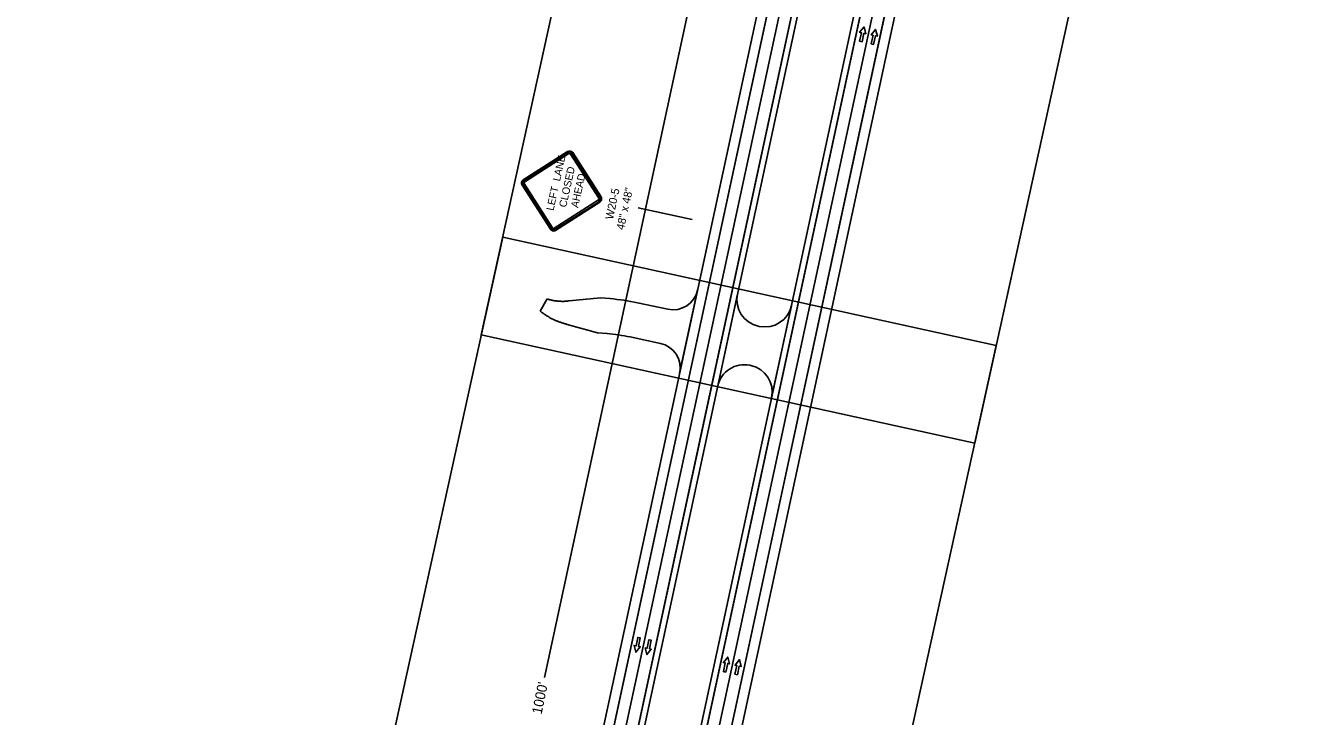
# Model space of a CAD drawing. Extents: x 14104283 to 14120882, y 8635219 to 8671666.
# Drawn here: x 14108141 to 14109426, y 8643764 to 8644454 of the extents above; entities that cross this region are included whole.
import ezdxf

# ---------------------------------------------------------------- set-up
doc = ezdxf.new("R2010")
doc.units = 0
for name, color, linetype in [('Cell', 7, 'Continuous'), ('dsnNonPlotable', 7, 'Continuous'), ('dsnPaintExistingEdgeLineRightWhite', 7, 'Continuous'), ('dsnPaintPlaceBrokenLineWhite', 7, 'Continuous'), ('dsnPaintPlaceEdgeLineLeftYellow', 7, 'Continuous'), ('dsnPaintPlaceEdgeLineRightWhite', 7, 'Continuous'), ('dsnPaintRemoveDoubleCenterLineYellow', 7, 'Continuous'), ('dsnShadingPaved', 7, 'Continuous'), ('dsnStdLabel', 7, 'Continuous'), ('dsnStgShadingPrevPav', 7, 'Continuous')]:
    doc.layers.add(name, color=color, linetype=linetype)

msp = doc.modelspace()

# ---------------------------------------------------------------- linework, layer by layer
at = {"layer": 'Cell'}
for p, q in [((14108682.3, 8644328.2), (14108638.1, 8644299.9)), ((14108682.8, 8644327.4), (14108683.7, 8644326.1)), ((14108685.4, 8644325.7), (14108686.7, 8644326.6)), ((14108715.8, 8644282.8), (14108687.5, 8644327.1)), ((14108637, 8644294.7), (14108665.3, 8644250.5)), ((14108637.8, 8644295.2), (14108639.1, 8644296.1)), ((14108639.5, 8644297.8), (14108638.6, 8644299.1)), ((14108670.4, 8644249.4), (14108714.7, 8644277.7)), ((14108713.3, 8644279.8), (14108714.2, 8644278.4)), ((14108715, 8644282.3), (14108713.7, 8644281.5)), ((14108667.4, 8644251.8), (14108666.1, 8644251)), ((14108669.9, 8644250.2), (14108669.1, 8644251.5))]:
    msp.add_line(p, q, dxfattribs=at)
for points in [[(14108976.7, 8644437.9), (14108974.3, 8644438.4), (14108976.1, 8644447), (14108974.3, 8644447.4), (14108978.7, 8644452.8), (14108980.4, 8644446), (14108978.6, 8644446.4)], [(14108988.3, 8644435.3), (14108985.9, 8644435.9), (14108987.7, 8644444.4), (14108985.9, 8644444.8), (14108990.3, 8644450.3), (14108992, 8644443.5), (14108990.2, 8644443.9)], [(14108682.8, 8644327.4), (14108638.6, 8644299.1), (14108639.5, 8644297.8), (14108683.7, 8644326.1), (14108682.8, 8644327.4)], [(14108715, 8644282.3), (14108686.7, 8644326.6), (14108685.4, 8644325.7), (14108713.7, 8644281.5), (14108715, 8644282.3)], [(14108637.8, 8644295.2), (14108666.1, 8644251), (14108667.4, 8644251.8), (14108639.1, 8644296.1), (14108637.8, 8644295.2)], [(14108669.9, 8644250.2), (14108714.2, 8644278.4), (14108713.3, 8644279.8), (14108669.1, 8644251.5), (14108669.9, 8644250.2)], [(14108752.6, 8643842.5), (14108755.1, 8643842), (14108753.2, 8643833.5), (14108755.1, 8643833.1), (14108750.7, 8643827.6), (14108748.9, 8643834.4), (14108750.8, 8643834)], [(14108763.7, 8643840.1), (14108766.1, 8643839.6), (14108764.3, 8643831), (14108766.1, 8643830.6), (14108761.7, 8643825.2), (14108760, 8643832), (14108761.8, 8643831.6)], [(14108840.5, 8643807.8), (14108838.1, 8643808.3), (14108839.9, 8643816.9), (14108838.1, 8643817.3), (14108842.5, 8643822.7), (14108844.2, 8643816), (14108842.4, 8643816.4)], [(14108852.2, 8643805.2), (14108849.7, 8643805.8), (14108851.6, 8643814.3), (14108849.8, 8643814.7), (14108854.1, 8643820.2), (14108855.9, 8643813.4), (14108854, 8643813.8)]]:
    msp.add_lwpolyline(points, close=True, dxfattribs=at)
for points in [[(14108978.6, 8644446.4), (14108980.4, 8644446), (14108978.7, 8644452.8), (14108974.3, 8644447.4), (14108976.1, 8644447), (14108974.3, 8644438.4), (14108976.7, 8644437.9), (14108978.6, 8644446.4)], [(14108990.2, 8644443.9), (14108992, 8644443.5), (14108990.3, 8644450.3), (14108985.9, 8644444.8), (14108987.7, 8644444.4), (14108985.9, 8644435.9), (14108988.3, 8644435.3), (14108990.2, 8644443.9)], [(14108750.8, 8643834), (14108748.9, 8643834.4), (14108750.7, 8643827.6), (14108755.1, 8643833.1), (14108753.2, 8643833.5), (14108755.1, 8643842), (14108752.6, 8643842.5), (14108750.8, 8643834)], [(14108761.8, 8643831.6), (14108760, 8643832), (14108761.7, 8643825.2), (14108766.1, 8643830.6), (14108764.3, 8643831), (14108766.1, 8643839.6), (14108763.7, 8643840.1), (14108761.8, 8643831.6)], [(14108842.4, 8643816.4), (14108844.2, 8643816), (14108842.5, 8643822.7), (14108838.1, 8643817.3), (14108839.9, 8643816.9), (14108838.1, 8643808.3), (14108840.5, 8643807.8), (14108842.4, 8643816.4)], [(14108854, 8643813.8), (14108855.9, 8643813.4), (14108854.1, 8643820.2), (14108849.8, 8643814.7), (14108851.6, 8643814.3), (14108849.7, 8643805.8), (14108852.2, 8643805.2), (14108854, 8643813.8)]]:
    msp.add_lwpolyline(points, dxfattribs=at)
for centre, radius, start, end in [((14108684.4, 8644325), 3.75, 32.608, 122.6076), ((14108684.4, 8644325), 2.81, 32.608, 122.6076), ((14108684.4, 8644325), 1.25, 32.608, 122.6076), ((14108640.1, 8644296.7), 3.75, 122.6078, 212.6076), ((14108640.1, 8644296.7), 2.81, 122.6078, 212.6076), ((14108640.1, 8644296.7), 1.25, 122.6078, 212.6076), ((14108712.7, 8644280.8), 1.25, 302.6078, 32.608), ((14108712.7, 8644280.8), 2.81, 302.6078, 32.608), ((14108712.7, 8644280.8), 3.75, 302.6078, 32.608), ((14108668.4, 8644252.5), 3.75, 212.6076, 302.6078), ((14108668.4, 8644252.5), 2.81, 212.6076, 302.6078), ((14108668.4, 8644252.5), 1.25, 212.6076, 302.6078)]:
    msp.add_arc(centre, radius, start, end, dxfattribs=at)
at = {"layer": 'dsnNonPlotable'}
for points in [[(14108596.1, 8644144.9), (14108932.5, 8645675.8), (14109425.7, 8645567.5), (14109089.3, 8644036.5)], [(14108281.2, 8642711.6), (14108617.6, 8644242.5), (14109110.8, 8644134.2), (14108774.4, 8642603.2)]]:
    msp.add_lwpolyline(points, close=True, dxfattribs=at)
at = {"layer": 'dsnPaintExistingEdgeLineRightWhite'}
msp.add_line((14108724, 8643185.8), (14109088.7, 8644879.7), dxfattribs=at)
at = {"layer": 'dsnPaintPlaceBrokenLineWhite'}
msp.add_line((14108623.3, 8643207.7), (14108988, 8644901.3), dxfattribs=at)
msp.add_lwpolyline([(14108306.4, 8641340.7), (14108389, 8641717), (14108712.3, 8643188.3), (14108894.6, 8644035.3), (14109077, 8644882.2)], dxfattribs=at)
at = {"layer": 'dsnPaintPlaceEdgeLineLeftYellow'}
msp.add_line((14108700.5, 8643190.8), (14109065.3, 8644884.7), dxfattribs=at)
msp.add_lwpolyline([(14108999.8, 8644898.8), (14108635.1, 8643205.1), (14108434.9, 8642294.1)], dxfattribs=at)
at = {"layer": 'dsnPaintPlaceEdgeLineRightWhite'}
msp.add_lwpolyline([(14108976.3, 8644903.9), (14108611.6, 8643210.2), (14108202.1, 8641346.1)], dxfattribs=at)
at = {"layer": 'dsnPaintRemoveDoubleCenterLineYellow'}
msp.add_lwpolyline([(14108306.4, 8641340.7), (14108389, 8641717), (14108712.3, 8643188.3), (14108894.6, 8644035.3), (14109077, 8644882.2)], dxfattribs=at)
at = {"layer": 'dsnShadingPaved'}
for points in [[(14108976.3, 8644903.9), (14108611.6, 8643210.2), (14108202.1, 8641346.1)], [(14108434.9, 8642294.1), (14108635.1, 8643205.1), (14108999.8, 8644898.8)]]:
    msp.add_lwpolyline(points, dxfattribs=at)
msp.add_lwpolyline([(14109065.3, 8644884.7), (14109088.7, 8644879.7), (14108724, 8643185.7), (14108700.5, 8643190.9)], close=True, dxfattribs=at)
at = {"layer": 'dsnStdLabel'}
for p, q in [((14108861.2, 8644740.1), (14108659.4, 8643802.5)), ((14108752.9, 8644272), (14108807, 8644260.1))]:
    msp.add_line(p, q, dxfattribs=at)
at = {"layer": 'dsnStgShadingPrevPav'}
for p, q in [((14108601.8, 8643212.3), (14108966.5, 8644906)), ((14108976.3, 8644903.9), (14108611.6, 8643210.2)), ((14109059.4, 8644886), (14108694.7, 8643192.1)), ((14108733.8, 8643183.6), (14109098.5, 8644877.6)), ((14108812.3, 8644189.7), (14108794.4, 8644106.6)), ((14108832.6, 8644093.8), (14108852.3, 8644185.7)), ((14108654.9, 8644168.7), (14108661.9, 8644180.9)), ((14108684, 8644178.9), (14108715.4, 8644182)), ((14108715.4, 8644182), (14108724.9, 8644181.2)), ((14108752.2, 8644177.1), (14108782.6, 8644170.5)), ((14108906.1, 8644174.1), (14108886.3, 8644082.2)), ((14108712.4, 8644147.1), (14108682, 8644155.4)), ((14108721.9, 8644146.3), (14108712.4, 8644147.1)), ((14108873.1, 8644153.6), (14108874, 8644153.4)), ((14108775.2, 8644136.3), (14108744.9, 8644142.9)), ((14108865.6, 8644114.3), (14108864.6, 8644114.5))]:
    msp.add_line(p, q, dxfattribs=at)
for points in [[(14108202.1, 8641346.1), (14108611.6, 8643210.2), (14108976.3, 8644903.9)], [(14108999.8, 8644898.8), (14108817.4, 8644052), (14108635.1, 8643205.1), (14108387.9, 8642080.1), (14108140.8, 8640955.1)], [(14108146.7, 8640953.8), (14108640.9, 8643203.9), (14109005.6, 8644897.6)], [(14108999.8, 8644898.8), (14108635.1, 8643205.1), (14108225.5, 8641340.9)]]:
    msp.add_lwpolyline(points, dxfattribs=at)
for centre, radius, start, end in [((14108787.9, 8644195), 25, 257.8488, 347.8488), ((14108878.7, 8644180), 27, 167.8488, 257.8488), ((14108706.4, 8643964.4), 217.5, 77.8488, 85.1347), ((14108879.7, 8644179.8), 27, 257.8488, 347.8488), ((14108706.4, 8643964.4), 182.5, 77.8488, 85.1347), ((14108770, 8644111.9), 25, 347.8488, 77.8488), ((14108858.9, 8644088.1), 27, 77.8488, 167.8488), ((14108859.9, 8644087.9), 27, 347.8488, 77.8488)]:
    msp.add_arc(centre, radius, start, end, dxfattribs=at)
for points in [[(14108661.9, 8644180.9), (14108662.2, 8644180.8), (14108663, 8644180.5), (14108664.1, 8644180.2), (14108665.2, 8644179.9), (14108666.3, 8644179.7), (14108667.5, 8644179.4), (14108668.6, 8644179.2), (14108669.7, 8644179), (14108670.8, 8644178.9), (14108671.9, 8644178.7), (14108673.1, 8644178.6), (14108674.2, 8644178.5), (14108675.3, 8644178.5), (14108676.4, 8644178.4), (14108677.5, 8644178.4), (14108678.6, 8644178.4), (14108679.7, 8644178.5), (14108680.8, 8644178.6), (14108681.8, 8644178.6), (14108682.9, 8644178.8), (14108683.6, 8644178.9), (14108684, 8644178.9)], [(14108682, 8644155.4), (14108681.5, 8644155.6), (14108680.5, 8644155.8), (14108679, 8644156.2), (14108677.5, 8644156.7), (14108676, 8644157.2), (14108674.5, 8644157.7), (14108673.1, 8644158.2), (14108671.7, 8644158.8), (14108670.3, 8644159.4), (14108668.9, 8644160), (14108667.5, 8644160.7), (14108666.1, 8644161.4), (14108664.8, 8644162.1), (14108663.5, 8644162.8), (14108662.2, 8644163.6), (14108660.9, 8644164.4), (14108659.7, 8644165.2), (14108658.5, 8644166), (14108657.3, 8644166.9), (14108656.1, 8644167.8), (14108655.3, 8644168.4), (14108654.9, 8644168.7)]]:
    msp.add_open_spline(points, degree=3, dxfattribs=at)

# ---------------------------------------------------------------- texts
at = {"layer": 'Cell'}
for s, height, p in [('LEFT  LANE', 7.5, (14108668.3, 8644268.6)), ('CLOSED', 7.5, (14108681, 8644271.9)), ('AHEAD', 7.5, (14108692.9, 8644271.5)), ('W20-5', 8, (14108727.7, 8644259.7)), ('48" x 48"', 8, (14108738.7, 8644249.3))]:
    msp.add_text(s, height=height, rotation=77.6078, dxfattribs=at).set_placement(p)
at = {"layer": 'dsnStdLabel'}
msp.add_text("1000'", height=10, rotation=78.5531, dxfattribs=at).set_placement((14108656.4, 8643765))

doc.saveas('drawing.dxf')
